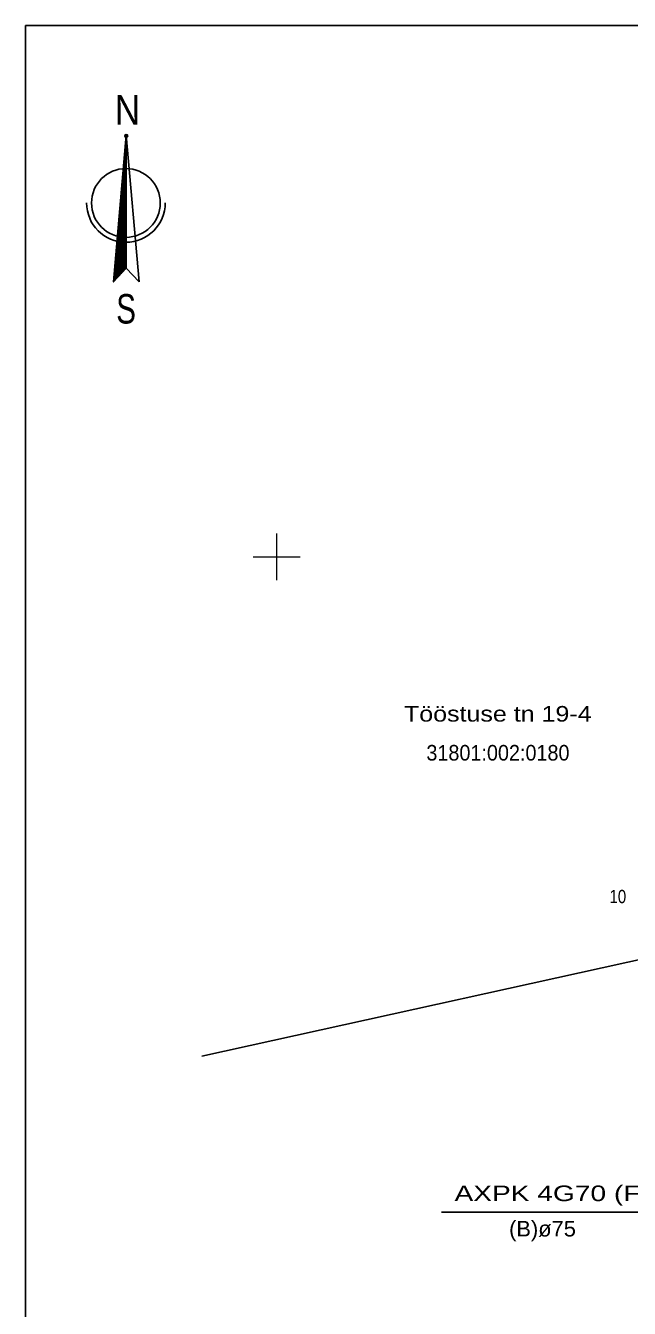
# Model space of a CAD drawing. Extents: x 543034 to 543126, y 6559741 to 6559884.
# Drawn here: x 543033.9 to 543072.6, y 6559801.8 to 6559884.1 of the extents above; entities that cross this region are included whole.
import ezdxf
from ezdxf.enums import TextEntityAlignment as Align

# ---------------------------------------------------------------- set-up
doc = ezdxf.new("R2010")
doc.units = 0
doc.header["$LTSCALE"] = 0.36
doc.header["$PDMODE"] = 32
doc.header["$PDSIZE"] = 0.18
for name, color, linetype, lineweight in [('15', 7, 'Continuous', 25), ('40', 7, 'Continuous', 25), ('58', 7, 'Continuous', 25), ('59', 7, 'Continuous', 13), ('63', 7, 'Continuous', 13)]:
    doc.layers.add(name, color=color, linetype=linetype, lineweight=lineweight)

msp = doc.modelspace()

# ---------------------------------------------------------------- linework, layer by layer
at = {"layer": '15'}
msp.add_line((543060.58, 6559807.95), (543080.89, 6559807.95), dxfattribs=at)
at = {"layer": '40'}
msp.add_lwpolyline([(543045.19, 6559817.96), (543078.56, 6559825.31), (543073.89, 6559855.56)], dxfattribs=at)
at = {"layer": '58'}
for p, q in [((543040.33, 6559876.83), (543040.35, 6559876.83)), ((543040.34, 6559876.93), (543040.35, 6559876.93)), ((543040.35, 6559877.08), (543041.18, 6559867.65)), ((543040.27, 6559876.17), (543040.35, 6559876.17)), ((543040.27, 6559876.07), (543040.35, 6559876.07)), ((543040.28, 6559876.26), (543040.35, 6559876.26)), ((543040.29, 6559876.36), (543040.35, 6559876.36)), ((543040.3, 6559876.45), (543040.35, 6559876.45)), ((543040.31, 6559876.55), (543040.35, 6559876.55)), ((543040.32, 6559876.74), (543040.35, 6559876.74)), ((543040.32, 6559876.64), (543040.35, 6559876.64)), ((543040.19, 6559875.22), (543040.35, 6559875.22)), ((543040.2, 6559875.32), (543040.35, 6559875.32)), ((543040.21, 6559875.41), (543040.35, 6559875.41)), ((543040.22, 6559875.51), (543040.35, 6559875.51)), ((543040.23, 6559875.7), (543040.35, 6559875.7)), ((543040.23, 6559875.6), (543040.35, 6559875.6)), ((543040.24, 6559875.79), (543040.35, 6559875.79)), ((543040.25, 6559875.88), (543040.35, 6559875.88)), ((543040.26, 6559875.98), (543040.35, 6559875.98)), ((543040.12, 6559874.37), (543040.35, 6559874.37)), ((543040.13, 6559874.56), (543040.35, 6559874.56)), ((543040.13, 6559874.47), (543040.35, 6559874.47)), ((543040.14, 6559874.65), (543040.35, 6559874.65)), ((543040.15, 6559874.75), (543040.35, 6559874.75)), ((543040.16, 6559874.84), (543040.35, 6559874.84)), ((543040.17, 6559874.94), (543040.35, 6559874.94)), ((543040.18, 6559875.13), (543040.35, 6559875.13)), ((543040.18, 6559875.03), (543040.35, 6559875.03)), ((543040.05, 6559873.61), (543040.35, 6559873.61)), ((543040.06, 6559873.71), (543040.35, 6559873.71)), ((543040.07, 6559873.8), (543040.35, 6559873.8)), ((543040.08, 6559873.99), (543040.35, 6559873.99)), ((543040.08, 6559873.9), (543040.35, 6559873.9)), ((543040.09, 6559874.09), (543040.35, 6559874.09)), ((543040.1, 6559874.18), (543040.35, 6559874.18)), ((543040.11, 6559874.28), (543040.35, 6559874.28)), ((543039.98, 6559872.76), (543040.35, 6559872.76)), ((543039.99, 6559872.95), (543040.35, 6559872.95)), ((543039.99, 6559872.86), (543040.35, 6559872.86)), ((543040, 6559873.05), (543040.35, 6559873.05)), ((543040.01, 6559873.14), (543040.35, 6559873.14)), ((543040.02, 6559873.24), (543040.35, 6559873.24)), ((543040.03, 6559873.42), (543040.35, 6559873.42)), ((543040.03, 6559873.33), (543040.35, 6559873.33)), ((543040.04, 6559873.52), (543040.35, 6559873.52)), ((543039.9, 6559871.91), (543040.35, 6559871.91)), ((543039.91, 6559872.01), (543040.35, 6559872.01)), ((543039.92, 6559872.1), (543040.35, 6559872.1)), ((543039.93, 6559872.19), (543040.35, 6559872.19)), ((543039.94, 6559872.38), (543040.35, 6559872.38)), ((543039.94, 6559872.29), (543040.35, 6559872.29)), ((543039.95, 6559872.48), (543040.35, 6559872.48)), ((543039.96, 6559872.57), (543040.35, 6559872.57)), ((543039.97, 6559872.67), (543040.35, 6559872.67)), ((543039.84, 6559871.25), (543040.35, 6559871.25)), ((543039.84, 6559871.15), (543040.35, 6559871.15)), ((543039.85, 6559871.34), (543040.35, 6559871.34)), ((543039.86, 6559871.44), (543040.35, 6559871.44)), ((543039.87, 6559871.53), (543040.35, 6559871.53)), ((543039.88, 6559871.63), (543040.35, 6559871.63)), ((543039.89, 6559871.82), (543040.35, 6559871.82)), ((543039.89, 6559871.72), (543040.35, 6559871.72)), ((543039.76, 6559870.3), (543040.35, 6559870.3)), ((543039.77, 6559870.4), (543040.35, 6559870.4)), ((543039.78, 6559870.49), (543040.35, 6559870.49)), ((543039.79, 6559870.68), (543040.35, 6559870.68)), ((543039.79, 6559870.59), (543040.35, 6559870.59)), ((543039.8, 6559870.78), (543040.35, 6559870.78)), ((543039.81, 6559870.87), (543040.35, 6559870.87)), ((543039.82, 6559870.96), (543040.35, 6559870.96)), ((543039.83, 6559871.06), (543040.35, 6559871.06)), ((543039.69, 6559869.45), (543040.35, 6559869.45)), ((543039.7, 6559869.64), (543040.35, 6559869.64)), ((543039.7, 6559869.55), (543040.35, 6559869.55)), ((543039.71, 6559869.73), (543040.35, 6559869.73)), ((543039.72, 6559869.83), (543040.35, 6559869.83)), ((543039.73, 6559869.92), (543040.35, 6559869.92)), ((543039.74, 6559870.11), (543040.35, 6559870.11)), ((543039.74, 6559870.02), (543040.35, 6559870.02)), ((543039.75, 6559870.21), (543040.35, 6559870.21)), ((543039.61, 6559868.6), (543040.35, 6559868.6)), ((543039.62, 6559868.69), (543040.35, 6559868.69)), ((543039.63, 6559868.79), (543040.35, 6559868.79)), ((543039.64, 6559868.88), (543040.35, 6559868.88)), ((543039.65, 6559869.07), (543040.35, 6559869.07)), ((543039.65, 6559868.98), (543040.35, 6559868.98)), ((543039.66, 6559869.17), (543040.35, 6559869.17)), ((543039.67, 6559869.26), (543040.35, 6559869.26)), ((543039.68, 6559869.36), (543040.35, 6559869.36)), ((543039.55, 6559867.94), (543039.79, 6559867.94)), ((543039.55, 6559867.84), (543039.7, 6559867.84)), ((543039.56, 6559868.03), (543039.88, 6559868.03)), ((543039.57, 6559868.13), (543039.97, 6559868.13)), ((543039.58, 6559868.22), (543040.06, 6559868.22)), ((543039.59, 6559868.32), (543040.14, 6559868.32)), ((543039.6, 6559868.5), (543040.32, 6559868.5)), ((543039.6, 6559868.41), (543040.23, 6559868.41)), ((543040.35, 6559868.54), (543041.18, 6559867.65)), ((543039.54, 6559867.75), (543039.62, 6559867.75))]:
    msp.add_line(p, q, dxfattribs=at)
for points in [[(543033.89, 6559884.1), (543126.39, 6559884.1), (543126.39, 6559740.6), (543033.89, 6559740.6)], [(543040.35, 6559877.08), (543039.53, 6559867.65), (543040.35, 6559868.54)]]:
    msp.add_lwpolyline(points, close=True, dxfattribs=at)
msp.add_circle((543040.3244, 6559872.7187), 2.2077, dxfattribs=at)
msp.add_arc((543040.3244, 6559872.7187), 2.5231, 180, 0, dxfattribs=at)
msp.add_point((543040.35, 6559877.02), dxfattribs=at)
at = {"layer": '63'}
for p, q in [((543050, 6559851.5), (543050, 6559848.5)), ((543048.5, 6559850), (543051.5, 6559850))]:
    msp.add_line(p, q, dxfattribs=at)

# ---------------------------------------------------------------- texts
at = {"layer": '15'}
for s, width, p in [('AXPK 4G70 (F2) -26.4-', 1.35, (543070.795, 6559808.65)), ('(B)ø75', 1.05, (543067.065, 6559806.38))]:
    msp.add_text(s, height=1, dxfattribs=dict(at, width=width)).set_placement(p, align=Align.CENTER)
at = {"layer": '40'}
for s, width, p in [('Tööstuse tn 19-4', 1.2, (543064.195, 6559839.43)), ('31801:002:0180', 0.95, (543064.205, 6559836.93))]:
    msp.add_text(s, height=1, dxfattribs=dict(at, width=width)).set_placement(p, align=Align.CENTER)
at = {"layer": '58'}
for s, width, p in [('N', 0.9, (543041.25, 6559877.75)), ('S', 0.75, (543040.97, 6559864.98))]:
    msp.add_text(s, height=1.892, dxfattribs=dict(at, width=width)).set_placement(p, align=Align.RIGHT)
at = {"layer": '59', "width": 0.85}
msp.add_text('10', height=0.85, dxfattribs=at).set_placement((543071.9, 6559827.78), align=Align.CENTER)

doc.saveas('drawing.dxf')
